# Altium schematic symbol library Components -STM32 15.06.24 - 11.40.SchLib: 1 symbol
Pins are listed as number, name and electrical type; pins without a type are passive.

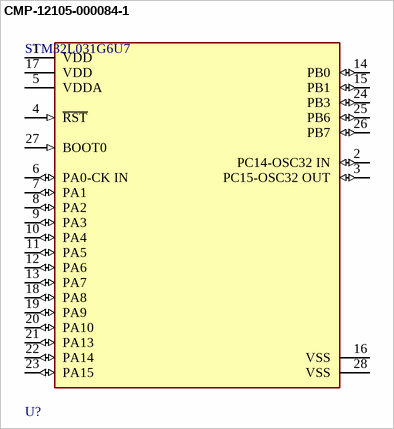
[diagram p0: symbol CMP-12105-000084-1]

## CMP-12105-000084-1
designator U?, comment STM32L031G6U7
IC MCU 32BIT 32KB FLASH 28UFQFPN; Oscillator Type: Internal; Core Architecture: ARM; Peripherals: Brown-out Detect/Reset; Interface: I2C; Watchdog Timer: Yes; Max Power Dissipation: 167mW; Max Frequency: 32MHz; Operating Supply Voltage: 3.3V; Number of Timers/Counters: 4; Max Supply Voltage: 3.6V; RAM Size: 1KB; Number of Programmable I/O: 21; Min Supply Voltage: 1.8V
footprint FP-UFQFPN28-A0B0-MFG
pins: 1 VDD (power), 2 PC14-OSC32 IN (io), 3 PC15-OSC32 OUT (io), 4 ~{RST} (in), 5 VDDA (power), 6 PA0-CK IN (io), 7 PA1 (io), 8 PA2 (io), 9 PA3 (io), 10 PA4 (io), 11 PA5 (io), 12 PA6 (io), 13 PA7 (io), 14 PB0 (io), 15 PB1 (io), 16 VSS (power), 17 VDD (power), 18 PA8 (io), 19 PA9 (io), 20 PA10 (io), 21 PA13 (io), 22 PA14 (io), 23 PA15 (io), 24 PB3 (io), 25 PB6 (io), 26 PB7 (io), 27 BOOT0 (in), 28 VSS (power)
